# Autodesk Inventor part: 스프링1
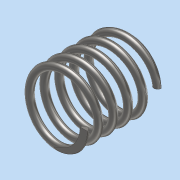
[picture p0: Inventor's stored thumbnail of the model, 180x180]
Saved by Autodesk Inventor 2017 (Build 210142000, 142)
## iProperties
Part Number: 스프링1
Material: 스테인레스 스틸
Document SubType Name: Modeling
Designer: MRC
Density: 8 g/cm^3
Appearance: 반연마
Mass: 6.57245 g
Surface Area: 16.7217 cm^2
Volume: 0.821556 cm^3
Author: MRC
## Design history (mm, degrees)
sketch "스케치1"
  geometry: L1 (0, 0)-(0, 20.5); L2 (0, 20.5)-(20.921, 20.5); L3 (0, 0)-(8.5, 0); C1 r 1 at (8.5, 0)
  constraints: 6 end point, 2 horizontal, 1 centre point, 1 coincident, 1 vertical
  dimensions: "d0" = 20.5 distance of L1.start L1.end (derived); "d1" = 8.5 distance of L1.start L3.end; "d2" = 2 diameter of C1
feature "코일1" sketch "스케치1" pitch "d3" = 10; turns "d5" = 5; dims "d4" = 20.5 (= d0), "d6" = 0, angle "d7" = 90 deg, angle "d8" = 90 deg, "d9" = 0, "d10" = 0
sketch "스케치2"
  geometry: L1 (20.5, 11.939)-(0, 11.939); L2 (0, 11.939)-(0, -12.02); L3 (0, -12.02)-(20.5, -12.02); L4 (20.5, -12.02)-(20.5, 11.939); 1 further point
  constraints: 8 end point, 2 parallel, 1 horizontal, 1 perpendicular, 1 point on line
  dimensions: "d11" = 20.5 distance of L2.end L3.end (= d0)
extrude "돌출1" sketch "스케치2" stored distance "d12" = 0; taper "d13" = 0 deg
node "솔리드1"
